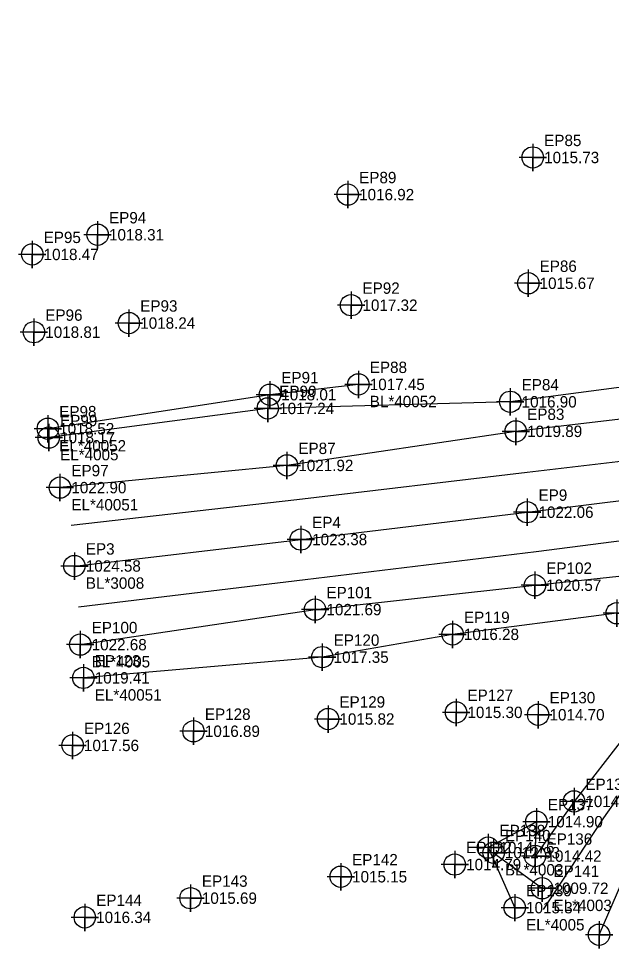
# Model space of a CAD drawing. Extents: x 1382561 to 1383039, y 884068 to 884307.
# Drawn here: x 1382560.9 to 1382691.1, y 884083.9 to 884288.1 of the extents above; entities that cross this region are included whole.
import ezdxf

# ---------------------------------------------------------------- set-up
doc = ezdxf.new("R2010")
doc.units = 0
for name, color, linetype in [('Exist DTM Breakline', 7, 'Continuous'), ('Exist DTM Breakline Cogo Comment', 7, 'Continuous'), ('Exist DTM Breakline Cogo Elevation', 7, 'Continuous'), ('Exist DTM Breakline Cogo Number', 7, 'Continuous'), ('Exist DTM Breakline Cogo Point CELL', 7, 'Continuous'), ('Exist DTM Breakline Underwater', 7, 'Continuous'), ('Exist DTM Breakline Underwater Cogo Point CELL', 7, 'Continuous'), ('Exist DTM Crownline', 7, 'Continuous'), ('Exist DTM Crownline Cogo Comment', 7, 'Continuous'), ('Exist DTM Crownline Cogo Elevation', 7, 'Continuous'), ('Exist DTM Crownline Cogo Number', 7, 'Continuous'), ('Exist DTM Crownline Cogo Point CELL', 7, 'Continuous'), ('Exist DTM Drainline', 7, 'Continuous'), ('Exist DTM Drainline Cogo Comment', 7, 'Continuous'), ('Exist DTM Drainline Cogo Elevation', 7, 'Continuous'), ('Exist DTM Drainline Cogo Number', 7, 'Continuous'), ('Exist DTM Drainline Cogo Point CELL', 7, 'Continuous'), ('Exist DTM Regular Point CELL', 7, 'Continuous'), ('Exist DTM Regular Point Cogo Elevation', 7, 'Continuous'), ('Exist DTM Regular Point Cogo Number', 7, 'Continuous'), ('Exist Hydro Stream or Body of Water', 7, 'Continuous'), ('Exist Roads EOP', 7, 'Continuous')]:
    doc.layers.add(name, color=color, linetype=linetype)

msp = doc.modelspace()

# ---------------------------------------------------------------- linework, layer by layer
at = {"layer": 'Exist DTM Breakline'}
for points in [[(1382806.7045, 884288.1336), (1382793.0575, 884267.4591), (1382781.8725, 884234.0918), (1382778.997, 884218.196), (1382773.7671, 884215.476), (1382722.2214, 884211.0337), (1382668.872, 884203.9756), (1382615.627, 884202.5184), (1382567.5113, 884196.1242)], [(1382635.5199, 884207.7962), (1382616.0865, 884205.5406), (1382567.3196, 884198.068)], [(1382774.3329, 884205.1982), (1382768.0574, 884207.1773), (1382721.0722, 884203.493), (1382670.0814, 884197.4905), (1382619.8383, 884190.0037), (1382569.9863, 884185.1279)], [(1382574.4485, 884150.6451), (1382626.0018, 884158.34), (1382674.2791, 884163.6957), (1382717.959, 884168.385), (1382736.7551, 884169.3534), (1382751.216, 884174.9855), (1382761.9845, 884178.8637)], [(1382765.9243, 884175.6081), (1382754.8134, 884167.9678), (1382731.7194, 884159.5309), (1382722.2333, 884160.3495), (1382705.5702, 884145.487), (1382682.8713, 884116.2267), (1382674.3334, 884104.2092), (1382674.6208, 884111.7647), (1382664.0032, 884106.0759), (1382669.8487, 884092.884)], [(1382732.2417, 884166.7349), (1382722.1245, 884160.9888), (1382692.2473, 884157.5499), (1382656.2039, 884152.9037), (1382627.5856, 884147.8988), (1382575.1219, 884143.3518)]]:
    msp.add_lwpolyline(points, dxfattribs=at)
at = {"layer": 'Exist DTM Breakline Cogo Point CELL'}
for points in [[(1382635.5199, 884210.7962), (1382635.5199, 884204.7962), (1382635.5199, 884207.7962), (1382638.5199, 884207.7962), (1382632.5199, 884207.7962)], [(1382616.0865, 884208.5406), (1382616.0865, 884202.5406), (1382616.0865, 884205.5406), (1382619.0865, 884205.5406), (1382613.0865, 884205.5406)], [(1382668.872, 884206.9756), (1382668.872, 884200.9756), (1382668.872, 884203.9756), (1382671.872, 884203.9756), (1382665.872, 884203.9756)], [(1382615.627, 884205.5184), (1382615.627, 884199.5184), (1382615.627, 884202.5184), (1382618.627, 884202.5184), (1382612.627, 884202.5184)], [(1382567.3196, 884201.068), (1382567.3196, 884195.068), (1382567.3196, 884198.068), (1382570.3196, 884198.068), (1382564.3196, 884198.068)], [(1382670.0814, 884200.4905), (1382670.0814, 884194.4905), (1382670.0814, 884197.4905), (1382673.0814, 884197.4905), (1382667.0814, 884197.4905)], [(1382567.5113, 884199.1242), (1382567.5113, 884193.1242), (1382567.5113, 884196.1242), (1382570.5113, 884196.1242), (1382564.5113, 884196.1242)], [(1382619.8383, 884193.0037), (1382619.8383, 884187.0037), (1382619.8383, 884190.0037), (1382622.8383, 884190.0037), (1382616.8383, 884190.0037)], [(1382569.9863, 884188.1279), (1382569.9863, 884182.1279), (1382569.9863, 884185.1279), (1382572.9863, 884185.1279), (1382566.9863, 884185.1279)], [(1382674.2791, 884166.6957), (1382674.2791, 884160.6957), (1382674.2791, 884163.6957), (1382677.2791, 884163.6957), (1382671.2791, 884163.6957)], [(1382626.0018, 884161.34), (1382626.0018, 884155.34), (1382626.0018, 884158.34), (1382629.0018, 884158.34), (1382623.0018, 884158.34)], [(1382692.2473, 884160.5499), (1382692.2473, 884154.5499), (1382692.2473, 884157.5499), (1382695.2473, 884157.5499), (1382689.2473, 884157.5499)], [(1382656.2039, 884155.9037), (1382656.2039, 884149.9037), (1382656.2039, 884152.9037), (1382659.2039, 884152.9037), (1382653.2039, 884152.9037)], [(1382574.4485, 884153.6451), (1382574.4485, 884147.6451), (1382574.4485, 884150.6451), (1382577.4485, 884150.6451), (1382571.4485, 884150.6451)], [(1382627.5856, 884150.8988), (1382627.5856, 884144.8988), (1382627.5856, 884147.8988), (1382630.5856, 884147.8988), (1382624.5856, 884147.8988)], [(1382575.1219, 884146.3518), (1382575.1219, 884140.3518), (1382575.1219, 884143.3518), (1382578.1219, 884143.3518), (1382572.1219, 884143.3518)], [(1382682.8713, 884119.2267), (1382682.8713, 884113.2267), (1382682.8713, 884116.2267), (1382685.8713, 884116.2267), (1382679.8713, 884116.2267)], [(1382674.6208, 884114.7647), (1382674.6208, 884108.7647), (1382674.6208, 884111.7647), (1382677.6208, 884111.7647), (1382671.6208, 884111.7647)], [(1382664.0032, 884109.0759), (1382664.0032, 884103.0759), (1382664.0032, 884106.0759), (1382667.0032, 884106.0759), (1382661.0032, 884106.0759)], [(1382674.3334, 884107.2092), (1382674.3334, 884101.2092), (1382674.3334, 884104.2092), (1382677.3334, 884104.2092), (1382671.3334, 884104.2092)], [(1382669.8487, 884095.884), (1382669.8487, 884089.884), (1382669.8487, 884092.884), (1382672.8487, 884092.884), (1382666.8487, 884092.884)]]:
    msp.add_lwpolyline(points, dxfattribs=at)
for centre in [(1382635.5199, 884207.7962), (1382616.0865, 884205.5406), (1382615.627, 884202.5184), (1382668.872, 884203.9756), (1382567.3196, 884198.068), (1382567.5113, 884196.1242), (1382670.0814, 884197.4905), (1382619.8383, 884190.0037), (1382569.9863, 884185.1279), (1382674.2791, 884163.6957), (1382626.0018, 884158.34), (1382692.2473, 884157.5499), (1382656.2039, 884152.9037), (1382574.4485, 884150.6451), (1382627.5856, 884147.8988), (1382575.1219, 884143.3518), (1382682.8713, 884116.2267), (1382674.6208, 884111.7647), (1382664.0032, 884106.0759), (1382674.3334, 884104.2092), (1382669.8487, 884092.884)]:
    msp.add_circle(centre, 2.344, dxfattribs=at)
at = {"layer": 'Exist DTM Breakline Underwater'}
msp.add_lwpolyline([(1382688.3783, 884086.9383), (1382699.504, 884112.5821), (1382721.2073, 884133.5617), (1382743.6214, 884142.6712), (1382769.5658, 884160.0329), (1382785.1067, 884174.8132), (1382789.3291, 884181.9565), (1382809.982, 884219.9732), (1382816.0046, 884242.1273), (1382837.3981, 884258.7844), (1382845.6113, 884276.5289)], dxfattribs=at)
at = {"layer": 'Exist DTM Breakline Underwater Cogo Point CELL'}
msp.add_lwpolyline([(1382688.3783, 884089.9383), (1382688.3783, 884083.9383), (1382688.3783, 884086.9383), (1382691.3783, 884086.9383), (1382685.3783, 884086.9383)], dxfattribs=at)
msp.add_circle((1382688.3783, 884086.9383), 2.344, dxfattribs=at)
at = {"layer": 'Exist DTM Crownline'}
msp.add_lwpolyline([(1382573.1626, 884167.9166), (1382622.8682, 884173.7315), (1382672.5741, 884179.7354), (1382722.0434, 884185.9092), (1382771.4612, 884191.9829)], dxfattribs=at)
at = {"layer": 'Exist DTM Crownline Cogo Point CELL'}
for points in [[(1382672.5741, 884182.7354), (1382672.5741, 884176.7354), (1382672.5741, 884179.7354), (1382675.5741, 884179.7354), (1382669.5741, 884179.7354)], [(1382622.8682, 884176.7315), (1382622.8682, 884170.7315), (1382622.8682, 884173.7315), (1382625.8682, 884173.7315), (1382619.8682, 884173.7315)], [(1382573.1626, 884170.9166), (1382573.1626, 884164.9166), (1382573.1626, 884167.9166), (1382576.1626, 884167.9166), (1382570.1626, 884167.9166)]]:
    msp.add_lwpolyline(points, dxfattribs=at)
for centre in [(1382672.5741, 884179.7354), (1382622.8682, 884173.7315), (1382573.1626, 884167.9166)]:
    msp.add_circle(centre, 2.344, dxfattribs=at)
at = {"layer": 'Exist DTM Drainline'}
msp.add_line((1382665.202, 884104.9568), (1382675.8548, 884097.1421), dxfattribs=at)
at = {"layer": 'Exist DTM Drainline Cogo Point CELL'}
for points in [[(1382665.202, 884107.9568), (1382665.202, 884101.9568), (1382665.202, 884104.9568), (1382668.202, 884104.9568), (1382662.202, 884104.9568)], [(1382675.8548, 884100.1421), (1382675.8548, 884094.1421), (1382675.8548, 884097.1421), (1382678.8548, 884097.1421), (1382672.8548, 884097.1421)]]:
    msp.add_lwpolyline(points, dxfattribs=at)
for centre in [(1382665.202, 884104.9568), (1382675.8548, 884097.1421)]:
    msp.add_circle(centre, 2.344, dxfattribs=at)
at = {"layer": 'Exist DTM Regular Point CELL'}
for points in [[(1382673.8173, 884260.6336), (1382673.8173, 884254.6336), (1382673.8173, 884257.6336), (1382676.8173, 884257.6336), (1382670.8173, 884257.6336)], [(1382633.1846, 884252.4747), (1382633.1846, 884246.4747), (1382633.1846, 884249.4747), (1382636.1846, 884249.4747), (1382630.1846, 884249.4747)], [(1382578.256, 884243.6574), (1382578.256, 884237.6574), (1382578.256, 884240.6574), (1382581.256, 884240.6574), (1382575.256, 884240.6574)], [(1382563.8987, 884239.3436), (1382563.8987, 884233.3436), (1382563.8987, 884236.3436), (1382566.8987, 884236.3436), (1382560.8987, 884236.3436)], [(1382672.814, 884233.0082), (1382672.814, 884227.0082), (1382672.814, 884230.0082), (1382675.814, 884230.0082), (1382669.814, 884230.0082)], [(1382633.9192, 884228.1917), (1382633.9192, 884222.1917), (1382633.9192, 884225.1917), (1382636.9192, 884225.1917), (1382630.9192, 884225.1917)], [(1382585.113, 884224.2732), (1382585.113, 884218.2732), (1382585.113, 884221.2732), (1382588.113, 884221.2732), (1382582.113, 884221.2732)], [(1382564.2599, 884222.2686), (1382564.2599, 884216.2686), (1382564.2599, 884219.2686), (1382567.2599, 884219.2686), (1382561.2599, 884219.2686)], [(1382628.8556, 884137.3113), (1382628.8556, 884131.3113), (1382628.8556, 884134.3113), (1382631.8556, 884134.3113), (1382625.8556, 884134.3113)], [(1382656.9713, 884138.7768), (1382656.9713, 884132.7768), (1382656.9713, 884135.7768), (1382659.9713, 884135.7768), (1382653.9713, 884135.7768)], [(1382674.9961, 884138.2584), (1382674.9961, 884132.2584), (1382674.9961, 884135.2584), (1382677.9961, 884135.2584), (1382671.9961, 884135.2584)], [(1382599.3077, 884134.6297), (1382599.3077, 884128.6297), (1382599.3077, 884131.6297), (1382602.3077, 884131.6297), (1382596.3077, 884131.6297)], [(1382572.7587, 884131.5159), (1382572.7587, 884125.5159), (1382572.7587, 884128.5159), (1382575.7587, 884128.5159), (1382569.7587, 884128.5159)], [(1382656.683, 884105.3589), (1382656.683, 884099.3589), (1382656.683, 884102.3589), (1382659.683, 884102.3589), (1382653.683, 884102.3589)], [(1382631.6376, 884102.6771), (1382631.6376, 884096.6771), (1382631.6376, 884099.6771), (1382634.6376, 884099.6771), (1382628.6376, 884099.6771)], [(1382598.6487, 884097.9683), (1382598.6487, 884091.9683), (1382598.6487, 884094.9683), (1382601.6487, 884094.9683), (1382595.6487, 884094.9683)], [(1382575.4365, 884093.7576), (1382575.4365, 884087.7576), (1382575.4365, 884090.7576), (1382578.4365, 884090.7576), (1382572.4365, 884090.7576)]]:
    msp.add_lwpolyline(points, dxfattribs=at)
for centre in [(1382673.8173, 884257.6336), (1382633.1846, 884249.4747), (1382578.256, 884240.6574), (1382563.8987, 884236.3436), (1382672.814, 884230.0082), (1382633.9192, 884225.1917), (1382585.113, 884221.2732), (1382564.2599, 884219.2686), (1382656.9713, 884135.7768), (1382674.9961, 884135.2584), (1382628.8556, 884134.3113), (1382599.3077, 884131.6297), (1382572.7587, 884128.5159), (1382656.683, 884102.3589), (1382631.6376, 884099.6771), (1382598.6487, 884094.9683), (1382575.4365, 884090.7576)]:
    msp.add_circle(centre, 2.344, dxfattribs=at)
at = {"layer": 'Exist Hydro Stream or Body of Water'}
msp.add_lwpolyline([(1382815.7469, 884285.0295), (1382796.5538, 884263.5381), (1382784.2894, 884233.9786), (1382781.1386, 884206.3096), (1382772.3397, 884180.9543), (1382766.7799, 884172.9781), (1382757.421, 884165.3571), (1382736.1951, 884155.0402), (1382706.3401, 884136.6072), (1382689.3837, 884112.6314), (1382676.096, 884092.4493)], dxfattribs=at)
at = {"layer": 'Exist Roads EOP'}
for points in [[(1382572.4495, 884176.8659), (1382622.0271, 884182.499), (1382672.5956, 884188.515), (1382721.14, 884194.2421), (1382775.6714, 884200.8541)], [(1382574.0878, 884158.9549), (1382623.8158, 884164.9302), (1382674.5802, 884171.138), (1382723.4333, 884177.3901), (1382767.3133, 884182.9042)]]:
    msp.add_lwpolyline(points, dxfattribs=at)

# ---------------------------------------------------------------- texts
at = {"layer": 'Exist DTM Breakline Cogo Comment'}
for s, p in [('BL*40052', (1382638.0199, 884202.7962)), ('EL*40052', (1382569.8196, 884193.068)), ('EL*4005', (1382570.0113, 884191.1242)), ('EL*40051', (1382572.4863, 884180.1279)), ('BL*4005', (1382576.9485, 884145.6451)), ('EL*40051', (1382577.6219, 884138.3518)), ('EL*4005', (1382672.3487, 884087.884))]:
    msp.add_text(s, height=2.5, dxfattribs=at).set_placement(p)
at = {"layer": 'Exist DTM Breakline Cogo Elevation'}
for s, p in [('1017.45', (1382638.0199, 884206.5462)), ('1018.01', (1382618.5865, 884204.2906)), ('1016.90', (1382671.372, 884202.7256)), ('1017.24', (1382618.127, 884201.2684)), ('1018.52', (1382569.8196, 884196.818)), ('1019.89', (1382672.5814, 884196.2405)), ('1018.17', (1382570.0113, 884194.8742)), ('1021.92', (1382622.3383, 884188.7537)), ('1022.90', (1382572.4863, 884183.8779)), ('1020.57', (1382676.7791, 884162.4457)), ('1021.69', (1382628.5018, 884157.09)), ('1016.28', (1382658.7039, 884151.6537)), ('1022.68', (1382576.9485, 884149.3951)), ('1017.35', (1382630.0856, 884146.6488)), ('1019.41', (1382577.6219, 884142.1018)), ('1014.68', (1382685.3713, 884114.9767)), ('1014.90', (1382677.1208, 884110.5147)), ('1014.76', (1382666.5032, 884104.8259)), ('1014.42', (1382676.8334, 884102.9592)), ('1015.34', (1382672.3487, 884091.634))]:
    msp.add_text(s, height=2.5, dxfattribs=at).set_placement(p)
at = {"layer": 'Exist DTM Breakline Cogo Number'}
for s, p in [('EP88', (1382638.0199, 884210.2962)), ('EP91', (1382618.5865, 884208.0406)), ('EP84', (1382671.372, 884206.4756)), ('EP90', (1382618.127, 884205.0184)), ('EP98', (1382569.8196, 884200.568)), ('EP83', (1382672.5814, 884199.9905)), ('EP99', (1382570.0113, 884198.6242)), ('EP87', (1382622.3383, 884192.5037)), ('EP97', (1382572.4863, 884187.6279)), ('EP102', (1382676.7791, 884166.1957)), ('EP101', (1382628.5018, 884160.84)), ('EP119', (1382658.7039, 884155.4037)), ('EP100', (1382576.9485, 884153.1451)), ('EP120', (1382630.0856, 884150.3988)), ('EP123', (1382577.6219, 884145.8518)), ('EP133', (1382685.3713, 884118.7267)), ('EP137', (1382677.1208, 884114.2647)), ('EP138', (1382666.5032, 884108.5759)), ('EP136', (1382676.8334, 884106.7092)), ('EP139', (1382672.3487, 884095.384))]:
    msp.add_text(s, height=2.5, dxfattribs=at).set_placement(p)
at = {"layer": 'Exist DTM Crownline Cogo Comment'}
msp.add_text('BL*3008', height=2.5, dxfattribs=at).set_placement((1382575.6626, 884162.9166))
at = {"layer": 'Exist DTM Crownline Cogo Elevation'}
for s, p in [('1022.06', (1382675.0741, 884178.4854)), ('1023.38', (1382625.3682, 884172.4815)), ('1024.58', (1382575.6626, 884166.6666))]:
    msp.add_text(s, height=2.5, dxfattribs=at).set_placement(p)
at = {"layer": 'Exist DTM Crownline Cogo Number'}
for s, p in [('EP9', (1382675.0741, 884182.2354)), ('EP4', (1382625.3682, 884176.2315)), ('EP3', (1382575.6626, 884170.4166))]:
    msp.add_text(s, height=2.5, dxfattribs=at).set_placement(p)
at = {"layer": 'Exist DTM Drainline Cogo Comment'}
for s, p in [('BL*4003', (1382667.702, 884099.9568)), ('EL*4003', (1382678.3548, 884092.1421))]:
    msp.add_text(s, height=2.5, dxfattribs=at).set_placement(p)
at = {"layer": 'Exist DTM Drainline Cogo Elevation'}
for s, p in [('1012.33', (1382667.702, 884103.7068)), ('1009.72', (1382678.3548, 884095.8921))]:
    msp.add_text(s, height=2.5, dxfattribs=at).set_placement(p)
at = {"layer": 'Exist DTM Drainline Cogo Number'}
for s, p in [('EP140', (1382667.702, 884107.4568)), ('EP141', (1382678.3548, 884099.6421))]:
    msp.add_text(s, height=2.5, dxfattribs=at).set_placement(p)
at = {"layer": 'Exist DTM Regular Point Cogo Elevation'}
for s, p in [('1015.73', (1382676.3173, 884256.3836)), ('1016.92', (1382635.6846, 884248.2247)), ('1018.31', (1382580.756, 884239.4074)), ('1018.47', (1382566.3987, 884235.0936)), ('1015.67', (1382675.314, 884228.7582)), ('1017.32', (1382636.4192, 884223.9417)), ('1018.24', (1382587.613, 884220.0232)), ('1018.81', (1382566.7599, 884218.0186)), ('1015.30', (1382659.4713, 884134.5268)), ('1015.82', (1382631.3556, 884133.0613)), ('1014.70', (1382677.4961, 884134.0084)), ('1016.89', (1382601.8077, 884130.3797)), ('1017.56', (1382575.2587, 884127.2659)), ('1014.79', (1382659.183, 884101.1089)), ('1015.15', (1382634.1376, 884098.4271)), ('1015.69', (1382601.1487, 884093.7183)), ('1016.34', (1382577.9365, 884089.5076))]:
    msp.add_text(s, height=2.5, dxfattribs=at).set_placement(p)
at = {"layer": 'Exist DTM Regular Point Cogo Number'}
for s, p in [('EP85', (1382676.3173, 884260.1336)), ('EP89', (1382635.6846, 884251.9747)), ('EP94', (1382580.756, 884243.1574)), ('EP95', (1382566.3987, 884238.8436)), ('EP86', (1382675.314, 884232.5082)), ('EP92', (1382636.4192, 884227.6917)), ('EP93', (1382587.613, 884223.7732)), ('EP96', (1382566.7599, 884221.7686)), ('EP129', (1382631.3556, 884136.8113)), ('EP127', (1382659.4713, 884138.2768)), ('EP130', (1382677.4961, 884137.7584)), ('EP128', (1382601.8077, 884134.1297)), ('EP126', (1382575.2587, 884131.0159)), ('EP132', (1382659.183, 884104.8589)), ('EP142', (1382634.1376, 884102.1771)), ('EP143', (1382601.1487, 884097.4683)), ('EP144', (1382577.9365, 884093.2576))]:
    msp.add_text(s, height=2.5, dxfattribs=at).set_placement(p)

doc.saveas('drawing.dxf')
